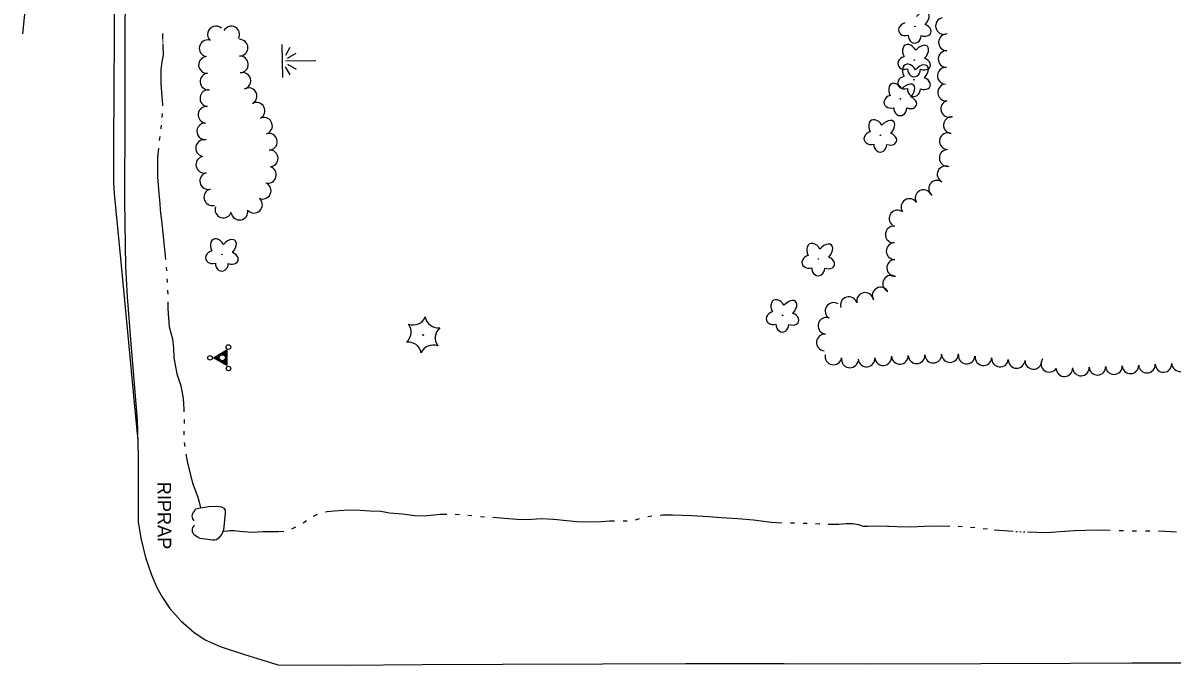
# Model space of a CAD drawing. Extents: x 589250 to 1188077, y 162953 to 363065.
# Drawn here: x 593086 to 593594, y 165078 to 165362 of the extents above; entities that cross this region are included whole.
import ezdxf

# ---------------------------------------------------------------- set-up
doc = ezdxf.new("R2010")
doc.units = 0
for name, color, linetype in [('E_DRN', 7, 'Continuous'), ('E_DRN_RipRap', 7, 'Continuous'), ('E_DRN_RipRap_Text', 7, 'Continuous'), ('E_LAND_TreeLine_P', 7, 'Continuous'), ('E_LAND_Vegetation', 7, 'Continuous'), ('E_MARK', 7, 'Continuous'), ('E_RDWY', 7, 'Continuous'), ('E_RDWY_Gravel', 7, 'Continuous'), ('E_WTR_FlowLine', 7, 'Continuous'), ('E_WTR_Wetland', 7, 'Continuous')]:
    doc.layers.add(name, color=color, linetype=linetype)

# ---------------------------------------------------------------- blocks, each defined once
blk = doc.blocks.new('POINT_DISPLAY')
blk.add_line((0, 0), (0, 0))

msp = doc.modelspace()

# ---------------------------------------------------------------- linework, layer by layer
at = {"layer": 'E_DRN'}
for centre, radius, start, end in [((593162.98, 165143.84), 2.53, 125.442, 231.7022), ((593163.23, 165137.8), 2.71, 128.6504, 234.9106)]:
    msp.add_arc(centre, radius, start, end, dxfattribs=at)
at = {"layer": 'E_DRN_RipRap'}
for p, q in [((593161.51, 165145.9), (593161.99, 165147.19)), ((593161.99, 165147.19), (593164.27, 165147.61)), ((593164.27, 165147.61), (593167.73, 165148.21)), ((593167.73, 165148.21), (593171.54, 165148.4)), ((593171.54, 165148.4), (593173.6, 165148.09)), ((593173.6, 165148.09), (593174.63, 165147.45)), ((593175.19, 165145.08), (593174.4, 165137.98)), ((593174.63, 165147.45), (593175.13, 165146.54)), ((593175.13, 165146.54), (593175.19, 165145.08)), ((593163.21, 165134.47), (593161.67, 165135.58)), ((593173.03, 165135.13), (593172.28, 165134.22)), ((593173.91, 165136.33), (593173.03, 165135.13)), ((593174.4, 165137.98), (593173.91, 165136.33)), ((593164.04, 165134.01), (593163.21, 165134.47)), ((593169.7, 165133.33), (593164.04, 165134.01)), ((593170.58, 165133.36), (593169.7, 165133.33)), ((593171.28, 165133.51), (593170.58, 165133.36)), ((593172.28, 165134.22), (593171.28, 165133.51))]:
    msp.add_line(p, q, dxfattribs=at)
at = {"layer": 'E_LAND_TreeLine_P'}
for centre, radius, start, end in [((593493.39, 165360.92), 3.7, 103.3322, 283.3322), ((593171.03, 165357.18), 3.69, 47.1415, 227.1415), ((593177.88, 165357.12), 3.69, 331.1778, 151.1778), ((593167.39, 165351.03), 3.69, 76.7838, 256.7838), ((593181.58, 165351.31), 3.69, 270.2324, 90.2324), ((593494.71, 165353.68), 3.7, 88.8074, 268.8074), ((593494.55, 165346.27), 3.7, 88.8074, 268.8074), ((593167.12, 165343.72), 3.69, 93.5988, 273.5988), ((593181.7, 165343.93), 3.69, 272.7772, 92.7772), ((593167.75, 165336.36), 3.69, 95.0764, 275.0764), ((593182.83, 165336.66), 3.69, 283.5811, 103.5811), ((593494.16, 165338.88), 3.7, 85.8337, 265.8337), ((593185.55, 165329.84), 3.69, 297.245, 117.245), ((593494.31, 165331.5), 3.7, 94.8906, 274.8906), ((593167.71, 165328.97), 3.69, 83.5225, 263.5225), ((593166.88, 165321.63), 3.69, 83.5225, 263.5225), ((593189.09, 165323.36), 3.69, 298.1833, 118.1833), ((593495.71, 165324.27), 3.7, 106.8197, 286.8197), ((593166.37, 165314.27), 3.69, 87.4212, 267.4212), ((593192.38, 165316.76), 3.69, 287.3943, 107.3943), ((593496.86, 165317.03), 3.7, 86.027, 266.027), ((593194.54, 165309.7), 3.69, 272.6172, 92.6172), ((593495.1, 165309.89), 3.7, 72.64, 252.64), ((593165.83, 165306.89), 3.71, 75.851, 255.851), ((593165.97, 165299.52), 3.71, 103.2876, 283.2876), ((593194.88, 165302.32), 3.69, 272.6172, 92.6172), ((593495.04, 165302.52), 3.7, 91.8927, 271.8927), ((593194.09, 165295.06), 3.71, 254.9109, 74.9109), ((593494.09, 165295.24), 3.7, 64.4917, 244.4917), ((593167.67, 165292.31), 3.71, 103.2876, 283.2876), ((593490.33, 165288.89), 3.7, 54.8521, 234.8521), ((593169.49, 165285.12), 3.71, 104.2686, 284.2686), ((593191.77, 165288.04), 3.71, 244.463, 64.463), ((593484.37, 165284.7), 3.7, 29.6908, 209.6908), ((593187.94, 165281.82), 3.71, 222.6686, 42.6686), ((593478.09, 165280.78), 3.7, 33.0233, 213.0233), ((593174.38, 165279.74), 3.71, 161.7974, 341.7974), ((593181.51, 165278.77), 3.71, 190.357, 10.357), ((593472.82, 165275.72), 3.7, 51.5726, 231.5726), ((593471.1, 165268.64), 3.7, 80.8603, 260.8603), ((593471.53, 165261.27), 3.7, 91.8975, 271.8975), ((593471.78, 165253.86), 3.7, 91.8975, 271.8975), ((593469.99, 165246.84), 3.7, 67.2069, 247.2069), ((593458.43, 165239.2), 3.7, 12.1436, 192.1436), ((593465.35, 165241.58), 3.7, 29.6214, 209.6214), ((593444.49, 165234.76), 3.7, 57.5329, 237.5329), ((593451.26, 165237.35), 3.7, 17.3627, 197.3627), ((593441.31, 165228.24), 3.7, 84.7175, 264.7175), ((593440.63, 165220.87), 3.7, 84.7175, 264.7175), ((593444.44, 165214.69), 3.7, 169.4481, 349.4481), ((593451.72, 165213.33), 3.7, 169.4481, 349.4481), ((593459.09, 165213.73), 3.7, 184.7701, 4.7701), ((593466.47, 165214.35), 3.7, 184.7701, 4.7701), ((593473.85, 165214.93), 3.7, 182.0325, 2.0325), ((593481.25, 165215.2), 3.7, 182.0325, 2.0325), ((593488.65, 165215.46), 3.7, 182.0325, 2.0325), ((593496.05, 165215.72), 3.7, 182.0325, 2.0325), ((593503.42, 165215.05), 3.7, 174.6724, 354.6724), ((593510.8, 165214.36), 3.7, 174.6724, 354.6724), ((593518.17, 165213.7), 3.7, 174.8766, 354.8766), ((593525.55, 165213.11), 3.7, 176.969, 356.969), ((593532.95, 165212.72), 3.7, 176.969, 356.969), ((593540.03, 165211.42), 3.7, 144.4685, 324.4685), ((593583.24, 165211.01), 3.66, 182.489, 2.489), ((593590.55, 165211.33), 3.66, 182.489, 2.489), ((593597.86, 165211.65), 3.66, 182.489, 2.489), ((593546.69, 165209.42), 3.66, 182.489, 2.489), ((593554, 165209.74), 3.66, 182.489, 2.489), ((593561.31, 165210.06), 3.66, 182.489, 2.489), ((593568.62, 165210.38), 3.66, 182.489, 2.489), ((593575.93, 165210.69), 3.66, 182.489, 2.489)]:
    msp.add_arc(centre, radius, start, end, dxfattribs=at)
at = {"layer": 'E_LAND_Vegetation'}
for centre, radius in [((593480.54, 165360.72), 0.128), ((593480.24, 165345.82), 0.128), ((593480.16, 165337.14), 0.128), ((593474.1, 165328.67), 0.128), ((593465.25, 165312.57), 0.128), ((593173.79, 165259.84), 0.128), ((593437.79, 165257.8), 0.128), ((593421.94, 165232.87), 0.128), ((593262.82, 165224.14), 0.167)]:
    msp.add_circle(centre, radius, dxfattribs=at)
for centre, radius, start, end in [((593258.36, 165234.5), 5.9, 250.4437, 336.2086), ((593269.56, 165233.19), 5.91, 190.4835, 276.1596), ((593251.62, 165225.45), 5.9, 310.4437, 36.2086), ((593274.02, 165222.83), 5.9, 130.4437, 216.2086), ((593256.14, 165215.14), 5.9, 10.4391, 96.204), ((593267.29, 165213.79), 5.9, 70.4437, 156.2086)]:
    msp.add_arc(centre, radius, start, end, dxfattribs=at)
for centre, major_axis, ratio in [((593483.12, 165363.34), (-3.19, -3.52), 0.560249), ((593476.82, 165359.52), (3.48, 0.97), 0.782863), ((593484.21, 165359.12), (-3.4, 1.25), 0.716896), ((593480.44, 165356.74), (0.07, 3.45), 0.832022), ((593478.32, 165348.78), (2.06, -3.68), 0.691916), ((593482.83, 165348.44), (-3.19, -3.52), 0.560249), ((593476.52, 165344.63), (3.48, 0.97), 0.782863), ((593478.23, 165340.1), (2.06, -3.68), 0.691916), ((593482.75, 165339.76), (-3.19, -3.52), 0.560249), ((593483.92, 165344.22), (-3.4, 1.25), 0.716896), ((593476.44, 165335.95), (3.48, 0.97), 0.782863), ((593480.15, 165341.84), (0.07, 3.45), 0.832022), ((593472.17, 165331.63), (2.06, -3.68), 0.691916), ((593476.68, 165331.29), (-3.19, -3.52), 0.560249), ((593480.07, 165333.16), (0.07, 3.45), 0.832022), ((593483.84, 165335.54), (-3.4, 1.25), 0.716896), ((593470.38, 165327.48), (3.48, 0.97), 0.782863), ((593477.77, 165327.07), (-3.4, 1.25), 0.716896), ((593474.01, 165324.69), (0.07, 3.45), 0.832022), ((593463.32, 165315.53), (2.06, -3.68), 0.691916), ((593467.83, 165315.19), (-3.19, -3.52), 0.560249), ((593461.53, 165311.37), (3.48, 0.97), 0.782863), ((593468.92, 165310.97), (-3.4, 1.25), 0.716896), ((593465.16, 165308.59), (0.07, 3.45), 0.832022), ((593171.87, 165262.8), (2.06, -3.68), 0.691916), ((593176.38, 165262.46), (-3.19, -3.52), 0.560249), ((593435.86, 165260.76), (2.06, -3.68), 0.691916), ((593440.37, 165260.42), (-3.19, -3.52), 0.560249), ((593170.08, 165258.64), (3.48, 0.97), 0.782863), ((593177.47, 165258.24), (-3.4, 1.25), 0.716896), ((593434.07, 165256.6), (3.48, 0.97), 0.782863), ((593441.47, 165256.2), (-3.4, 1.25), 0.716896), ((593173.7, 165255.86), (0.07, 3.45), 0.832022), ((593437.7, 165253.82), (0.07, 3.45), 0.832022), ((593420.01, 165235.83), (2.06, -3.68), 0.691916), ((593424.52, 165235.49), (-3.19, -3.52), 0.560249), ((593418.22, 165231.67), (3.48, 0.97), 0.782863), ((593425.62, 165231.27), (-3.4, 1.25), 0.716896), ((593421.85, 165228.88), (0.07, 3.45), 0.832022)]:
    msp.add_ellipse(centre, major_axis=major_axis, ratio=ratio, start_param=1.570796, end_param=4.712389, dxfattribs=at)
at = {"layer": 'E_MARK'}
for p, q in [((593169.94, 165214.05), (593175.88, 165217.59)), ((593170.22, 165214.05), (593175.72, 165217.31)), ((593170.58, 165214.05), (593175.57, 165217.03)), ((593170.86, 165214.05), (593175.41, 165216.75)), ((593171.14, 165214.05), (593175.25, 165216.47)), ((593175.25, 165216.47), (593175.27, 165211.67)), ((593175.25, 165216.47), (593175.25, 165216.47)), ((593175.41, 165216.75), (593175.43, 165211.43)), ((593175.41, 165216.75), (593175.41, 165216.75)), ((593175.57, 165217.03), (593175.59, 165211.19)), ((593175.57, 165217.03), (593175.57, 165217.03)), ((593175.72, 165217.31), (593175.75, 165210.87)), ((593175.72, 165217.31), (593175.72, 165217.31)), ((593175.88, 165217.59), (593175.91, 165210.63)), ((593175.88, 165217.59), (593175.88, 165217.59)), ((593175.91, 165210.63), (593169.94, 165214.05)), ((593175.75, 165210.87), (593170.22, 165214.05)), ((593175.59, 165211.19), (593170.58, 165214.05)), ((593175.43, 165211.43), (593170.86, 165214.05)), ((593175.27, 165211.67), (593171.14, 165214.05))]:
    msp.add_line(p, q, dxfattribs=at)
for centre, radius in [((593173.9, 165214.07), 2), ((593176.61, 165218.8), 1), ((593168.44, 165214.04), 1), ((593173.9, 165214.07), 1.84), ((593173.9, 165214.07), 1.68), ((593173.9, 165214.07), 1.52), ((593173.9, 165214.07), 1.36), ((593176.65, 165209.35), 1)]:
    msp.add_circle(centre, radius, dxfattribs=at)
at = {"layer": 'E_RDWY'}
for p, q in [((593085.67, 165357.39), (593088.74, 165389.55)), ((593125.98, 165373.67), (593125.99, 165356.92)), ((593125.99, 165356.92), (593125.71, 165307.77)), ((593125.71, 165307.77), (593125.71, 165291.49)), ((593125.71, 165291.49), (593126.11, 165286.58)), ((593126.11, 165286.58), (593128.83, 165258.03)), ((593128.83, 165258.03), (593132.16, 165223.9)), ((593132.16, 165223.9), (593134.94, 165194.14)), ((593134.94, 165194.14), (593136.44, 165177.43)), ((593136.44, 165177.43), (593136.7, 165168.5)), ((593136.7, 165168.5), (593136.71, 165141.52)), ((593136.71, 165141.52), (593137.82, 165134.21)), ((593137.82, 165134.21), (593139.97, 165125.69)), ((593139.97, 165125.69), (593142.54, 165117.95)), ((593142.54, 165117.95), (593145.09, 165112.1)), ((593145.09, 165112.1), (593147.39, 165107.96)), ((593147.39, 165107.96), (593150.71, 165103.06)), ((593150.71, 165103.06), (593155.54, 165097.7)), ((593155.54, 165097.7), (593161.26, 165092.66)), ((593161.26, 165092.66), (593166.31, 165089.26)), ((593166.31, 165089.26), (593172.94, 165086.34)), ((593172.94, 165086.34), (593183.72, 165082.8)), ((593183.72, 165082.8), (593195.3, 165079.21)), ((593195.3, 165079.21), (593198.44, 165078.14)), ((593342.15, 165078.66), (593379.04, 165078.72)), ((593379.04, 165078.72), (593422.59, 165078.8)), ((593422.59, 165078.8), (593461.03, 165078.64)), ((593461.03, 165078.64), (593509.74, 165078.77)), ((593509.74, 165078.77), (593549.44, 165078.9)), ((593549.44, 165078.9), (593576.47, 165079.1)), ((593576.47, 165079.1), (593602.87, 165079.06)), ((593198.44, 165078.14), (593227.89, 165078.07)), ((593227.89, 165078.07), (593262.57, 165078.28)), ((593262.57, 165078.28), (593297.94, 165078.39)), ((593297.94, 165078.39), (593342.15, 165078.66))]:
    msp.add_line(p, q, dxfattribs=at)
at = {"layer": 'E_RDWY_Gravel'}
for p, q in [((593131.02, 165381.44), (593130.82, 165357.52)), ((593130.82, 165357.52), (593130.73, 165322.04)), ((593130.73, 165322.04), (593130.65, 165283.39)), ((593130.65, 165283.39), (593131.06, 165254.36)), ((593131.06, 165254.36), (593131.73, 165241.05)), ((593131.73, 165241.05), (593133.43, 165220.35)), ((593133.43, 165220.35), (593136.27, 165186.41)), ((593136.27, 165186.41), (593136.48, 165175.91))]:
    msp.add_line(p, q, dxfattribs=at)
at = {"layer": 'E_WTR_FlowLine'}
for p, q in [((593147.62, 165354.93), (593147.53, 165357.64)), ((593147.64, 165354.37), (593147.64, 165354.56)), ((593147.66, 165353.81), (593147.66, 165354)), ((593147.68, 165353.25), (593147.68, 165353.44)), ((593147.79, 165350.17), (593147.66, 165348.15)), ((593147.79, 165350.17), (593147.7, 165352.88)), ((593147.17, 165345.12), (593146.74, 165341.57)), ((593147.66, 165348.15), (593147.17, 165345.12)), ((593146.74, 165341.57), (593146.65, 165335.36)), ((593146.65, 165335.36), (593147.45, 165325.98)), ((593147.45, 165325.98), (593147.43, 165325.54)), ((593147.28, 165322.13), (593147.21, 165320.42)), ((593146.86, 165317.03), (593146.64, 165315.34)), ((593146.22, 165311.95), (593146.02, 165310.26)), ((593145.66, 165306.87), (593145.29, 165302.89)), ((593145.29, 165302.89), (593145.29, 165294.21)), ((593145.29, 165294.21), (593145.82, 165286.74)), ((593145.82, 165286.74), (593146.21, 165282.18)), ((593146.21, 165282.18), (593146.44, 165279.58)), ((593146.44, 165279.58), (593147.2, 165273.46)), ((593147.2, 165273.46), (593147.99, 165264.96)), ((593147.99, 165264.96), (593148.76, 165257.58)), ((593149.02, 165254.18), (593149.15, 165252.48)), ((593149.38, 165249.07), (593149.48, 165247.37)), ((593149.7, 165243.96), (593149.72, 165243.56)), ((593149.72, 165243.56), (593149.74, 165242.26)), ((593149.78, 165238.85), (593149.81, 165235.73)), ((593149.81, 165235.73), (593150.4, 165227.7)), ((593150.4, 165227.7), (593151.83, 165222.48)), ((593151.83, 165222.48), (593152.26, 165218.26)), ((593152.26, 165218.26), (593152.48, 165214.35)), ((593152.48, 165214.35), (593152.54, 165213.34)), ((593152.54, 165213.34), (593153.83, 165206.89)), ((593153.83, 165206.89), (593155.55, 165201.59)), ((593155.55, 165201.59), (593156.54, 165196.11)), ((593156.54, 165196.11), (593156.88, 165191.22)), ((593156.88, 165191.22), (593156.9, 165190.12)), ((593156.96, 165186.71), (593156.99, 165185)), ((593156.93, 165181.59), (593156.88, 165179.89)), ((593157.08, 165176.49), (593157.26, 165174.79)), ((593157.7, 165171.41), (593158.48, 165167.59)), ((593158.48, 165167.59), (593159.82, 165162.14)), ((593159.82, 165162.14), (593160.83, 165158.33)), ((593160.83, 165158.33), (593161.93, 165155.49)), ((593161.93, 165155.49), (593163.05, 165152.36)), ((593163.05, 165152.36), (593163.71, 165150.19)), ((593163.71, 165150.19), (593164.27, 165147.61)), ((593214.34, 165143.98), (593215.98, 165144.86)), ((593219.55, 165145.87), (593220.27, 165146.05)), ((593220.27, 165146.05), (593223.43, 165146.35)), ((593223.43, 165146.35), (593227.65, 165146.66)), ((593227.65, 165146.66), (593230.91, 165146.77)), ((593230.91, 165146.77), (593234.81, 165146.66)), ((593234.81, 165146.66), (593239.15, 165146.3)), ((593239.15, 165146.3), (593244.05, 165146.14)), ((593244.05, 165146.14), (593246.45, 165145.74)), ((593246.45, 165145.74), (593247.95, 165145.49)), ((593247.95, 165145.49), (593253.61, 165144.92)), ((593253.61, 165144.92), (593259.16, 165144.18)), ((593267.57, 165144.54), (593270.36, 165144.84)), ((593270.36, 165144.84), (593273.3, 165144.87)), ((593277.03, 165144.84), (593278.89, 165144.76)), ((593209.65, 165140.96), (593211.15, 165142.06)), ((593259.16, 165144.18), (593263.38, 165144.08)), ((593263.38, 165144.08), (593267.57, 165144.54)), ((593282.6, 165144.47), (593284.44, 165144.24)), ((593288.15, 165143.87), (593290, 165143.73)), ((593293.72, 165143.49), (593297.14, 165143.28)), ((593297.14, 165143.28), (593300.54, 165142.97)), ((593300.54, 165142.97), (593304.5, 165142.67)), ((593304.5, 165142.67), (593308.75, 165142.54)), ((593308.75, 165142.54), (593315.23, 165142.86)), ((593315.23, 165142.86), (593320.33, 165142.7)), ((593320.33, 165142.7), (593320.67, 165142.67)), ((593320.67, 165142.67), (593326.49, 165142.08)), ((593326.49, 165142.08), (593330.92, 165141.57)), ((593330.92, 165141.57), (593337.2, 165141.39)), ((593337.2, 165141.39), (593341.65, 165141.61)), ((593341.65, 165141.61), (593345.32, 165141.86)), ((593345.32, 165141.86), (593347.59, 165141.92)), ((593351.31, 165141.95), (593353.17, 165141.93)), ((593356.87, 165142.4), (593358.66, 165142.91)), ((593362.27, 165143.79), (593364.11, 165144.09)), ((593367.81, 165144.42), (593368.94, 165144.48)), ((593368.94, 165144.48), (593373.22, 165144.5)), ((593373.22, 165144.5), (593381.79, 165144.24)), ((593381.79, 165144.24), (593389.21, 165143.77)), ((593389.21, 165143.77), (593394.78, 165143.4)), ((593394.78, 165143.4), (593402.11, 165142.92)), ((593402.11, 165142.92), (593409.01, 165142.27)), ((593409.01, 165142.27), (593416.93, 165141.27)), ((593416.93, 165141.27), (593421.66, 165141.07)), ((593425.38, 165140.97), (593427.24, 165140.96)), ((593430.97, 165140.93), (593432.83, 165140.85)), ((593436.55, 165140.7), (593438.25, 165140.63)), ((593438.25, 165140.63), (593438.41, 165140.62)), ((593442.12, 165140.37), (593442.36, 165140.35)), ((593442.36, 165140.35), (593446.9, 165140.37)), ((593446.9, 165140.37), (593450.12, 165140.65)), ((593450.12, 165140.65), (593453.03, 165140.75)), ((593453.03, 165140.75), (593455.49, 165140.26)), ((593455.49, 165140.26), (593457.55, 165139.5)), ((593174.25, 165137.46), (593175.67, 165137.28)), ((593175.67, 165137.28), (593177.02, 165137.54)), ((593177.02, 165137.54), (593179.02, 165137.55)), ((593179.02, 165137.55), (593183.06, 165137.1)), ((593183.06, 165137.1), (593187.29, 165136.82)), ((593187.29, 165136.82), (593189.69, 165137.01)), ((593189.69, 165137.01), (593191.92, 165137.14)), ((593191.92, 165137.14), (593194.88, 165137.18)), ((593194.88, 165137.18), (593198.75, 165137.13)), ((593198.75, 165137.13), (593201.15, 165137.34)), ((593204.69, 165138.41), (593206.39, 165139.17)), ((593457.55, 165139.5), (593459.54, 165139.48)), ((593459.54, 165139.48), (593463.03, 165139.73)), ((593463.03, 165139.73), (593468.43, 165139.49)), ((593468.43, 165139.49), (593468.91, 165139.48)), ((593468.91, 165139.48), (593472.65, 165139.39)), ((593472.65, 165139.39), (593478.78, 165139.27)), ((593478.78, 165139.27), (593484.64, 165139.47)), ((593484.64, 165139.47), (593491.09, 165139.64)), ((593491.09, 165139.64), (593495.9, 165139.57)), ((593499.62, 165139.47), (593501.48, 165139.41)), ((593505.19, 165139.11), (593507.04, 165138.94)), ((593510.74, 165138.52), (593512.59, 165138.28)), ((593515.59, 165137.89), (593524, 165137.32)), ((593525.16, 165137.24), (593525.74, 165137.2)), ((593526.9, 165137.12), (593527.48, 165137.08)), ((593528.64, 165137.01), (593529.22, 165136.99)), ((593530.39, 165136.96), (593538.82, 165136.71)), ((593538.82, 165136.71), (593551.05, 165137.63)), ((593551.05, 165137.63), (593561.04, 165137.86)), ((593561.04, 165137.86), (593566.99, 165137.71)), ((593570.88, 165137.61), (593572.82, 165137.56)), ((593576.71, 165137.52), (593578.66, 165137.51)), ((593582.55, 165137.5), (593584.5, 165137.49)), ((593588.39, 165137.47), (593588.52, 165137.47)), ((593588.52, 165137.47), (593596.24, 165137.08))]:
    msp.add_line(p, q, dxfattribs=at)
at = {"layer": 'E_WTR_Wetland'}
for p, q in [((593200.32, 165352.67), (593200.51, 165338.11)), ((593203.85, 165351.46), (593201.84, 165347.81)), ((593202.77, 165346.74), (593206.54, 165348.96)), ((593215.24, 165345.55), (593202.04, 165345.38)), ((593202.81, 165343.98), (593206.63, 165341.87)), ((593204.01, 165339.29), (593201.91, 165342.89))]:
    msp.add_line(p, q, dxfattribs=at)

# ---------------------------------------------------------------- block references
at = {"layer": 'E_WTR_Wetland', "rotation": 89.2570511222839}
for p in [(593200.41, 165345.83), (593200.41, 165345.34), (593200.41, 165345.28), (593202.04, 165345.38), (593203.29, 165345.4)]:
    msp.add_blockref('POINT_DISPLAY', p, dxfattribs=at)

# ---------------------------------------------------------------- texts
at = {"layer": 'E_DRN_RipRap_Text'}
msp.add_text('RIPRAP', height=6, rotation=270.2324, dxfattribs=at).set_placement((593145.2, 165159.17))

doc.saveas('drawing.dxf')
